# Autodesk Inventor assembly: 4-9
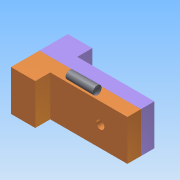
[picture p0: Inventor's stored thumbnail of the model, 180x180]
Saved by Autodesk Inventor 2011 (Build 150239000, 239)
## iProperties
Created: 2014-03
Part Number: 4-9
Document SubType Name: Assembly
Designer: Administrator
Author: Administrator
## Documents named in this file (3)
- J:\新作模型\4-9.iam
- J:\新作模型\4-9a.ipt
- J:\新作模型\4-9锥形销 GB_T 117 A 6 x 22.ipt
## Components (3 placed, 2 different names)
1. 4-9a:1 — 配合:1, 表面齐平:1, 表面齐平:2
2. 4-9a:2 — 配合:1, 表面齐平:1, 表面齐平:2
3. 4-9锥形销 GB_T 117 A 6 x 22:1
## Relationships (3: Flush 2, Mate 1)
- 配合:1 [Mate]: 4-9a:1 ↔ 4-9a:2
- 表面齐平:1 [Flush]: 4-9a:1 ↔ 4-9a:2
- 表面齐平:2 [Flush]: 4-9a:1 ↔ 4-9a:2
